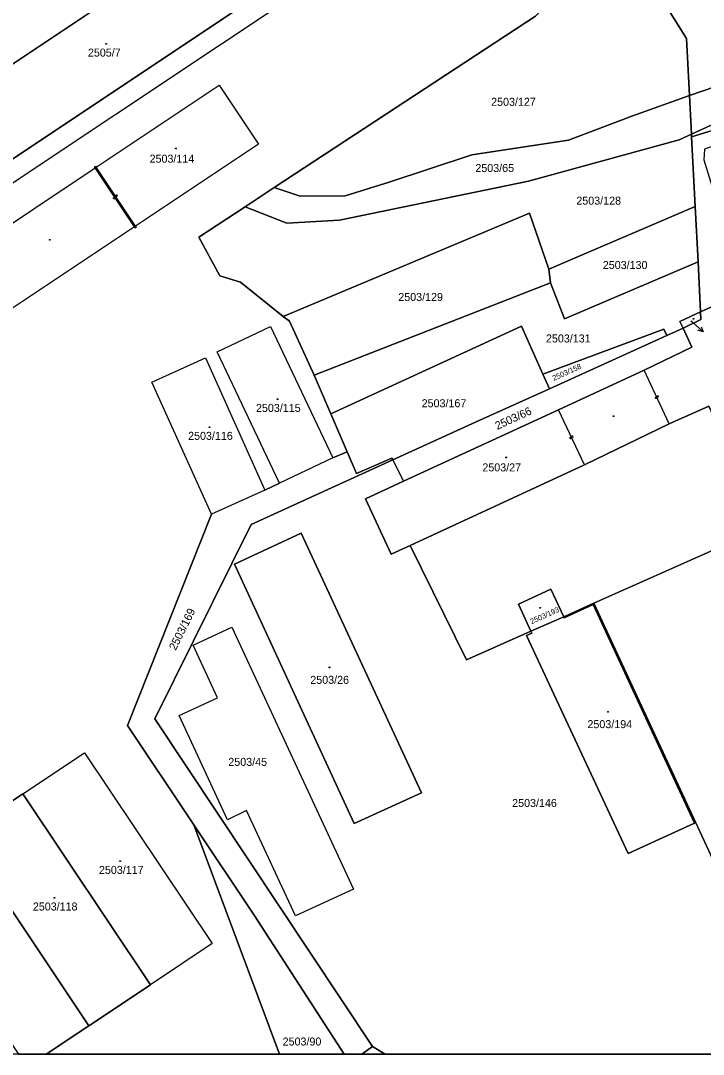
# Model space of a CAD drawing. Extents: x -596024 to -594475, y -1163820 to -1161957.
# Drawn here: x -595859.9 to -595715, y -1163820.2 to -1163600.7 of the extents above; entities that cross this region are included whole.
import ezdxf

# ---------------------------------------------------------------- set-up
doc = ezdxf.new("R2010")
doc.units = 0
for name, color, linetype in [('Level 1', 7, 'Continuous'), ('Level 13', 7, 'Continuous'), ('Level 3', 7, 'Continuous'), ('Level 4', 7, 'Continuous'), ('Level 5', 7, 'Continuous'), ('Level 57', 7, 'Continuous'), ('Level 60', 7, 'Continuous'), ('Vrstva 60', 7, 'Continuous'), ('Vrstva 63', 7, 'Continuous')]:
    doc.layers.add(name, color=color, linetype=linetype)

msp = doc.modelspace()

# ---------------------------------------------------------------- linework, layer by layer
at = {"layer": 'Level 1'}
for p, q in [((-595804.96, -1163820.23), (-595823.13, -1163771.52)), ((-595845.44, -1163814.2), (-595854.47, -1163820.23)), ((-595787.47, -1163820.23), (-595785.2, -1163818.59)), ((-595782.49, -1163820.23), (-595785.2, -1163818.59))]:
    msp.add_line(p, q, dxfattribs=at)
for points in [[(-595747.71, -1163559.45), (-595779.54, -1163580.65), (-595794.81, -1163590.75), (-595884.83, -1163650.71), (-595898.68, -1163630.68)], [(-595882.06, -1163623.58), (-595809.58, -1163575.23), (-595800.28, -1163589.15), (-595877.77, -1163640.84), (-595886.1, -1163628.4)], [(-595732.35, -1163582.47), (-595718.5, -1163604.56), (-595717.89, -1163616.66)], [(-595750.6, -1163599.77), (-595806.04, -1163636.18)], [(-595694.99, -1163605.67), (-595707.37, -1163613.03), (-595717.89, -1163616.66)], [(-595683.26, -1163606.91), (-595697.36, -1163615.67), (-595717.47, -1163624.86)], [(-595666.6, -1163609.76), (-595717.44, -1163625.43)], [(-595843.85, -1163631.82), (-595817.77, -1163614.42), (-595809.41, -1163626.95), (-595835.49, -1163644.35)], [(-595717.89, -1163616.66), (-595730.15, -1163621.02), (-595743.61, -1163626.13), (-595764.11, -1163629.2), (-595781.68, -1163635.06), (-595791.02, -1163637.97), (-595800.58, -1163638), (-595806.04, -1163636.18)], [(-595717.47, -1163624.86), (-595717.89, -1163616.66)], [(-595812.22, -1163640.24), (-595803.39, -1163643.76), (-595792.23, -1163643.09), (-595752.06, -1163634.84), (-595720.06, -1163626.04), (-595717.47, -1163624.86)], [(-595717.44, -1163625.43), (-595717.47, -1163624.86)], [(-595716.69, -1163640.21), (-595717.44, -1163625.43)], [(-595835.74, -1163644.51), (-595861.82, -1163661.91), (-595870.18, -1163649.38), (-595844.07, -1163631.97)], [(-595844.07, -1163631.97), (-595844.21, -1163631.76), (-595843.99, -1163631.61), (-595843.85, -1163631.82)], [(-595806.04, -1163636.18), (-595812.22, -1163640.24)], [(-595812.22, -1163640.24), (-595822.04, -1163646.69), (-595817.61, -1163654.91), (-595813.25, -1163656.26), (-595804.17, -1163663.57)], [(-595716.69, -1163640.21), (-595747.78, -1163653.48)], [(-595716.09, -1163651.96), (-595716.69, -1163640.21)], [(-595747.78, -1163653.48), (-595751.85, -1163641.63), (-595804.17, -1163663.57)], [(-595835.49, -1163644.35), (-595835.31, -1163644.61), (-595835.55, -1163644.81), (-595835.74, -1163644.51)], [(-595747.43, -1163656.44), (-595744.41, -1163664.02), (-595716.09, -1163651.96)], [(-595715.55, -1163662.6), (-595716.09, -1163651.96)], [(-595747.78, -1163653.48), (-595747.43, -1163656.44)], [(-595797.59, -1163676.03), (-595747.43, -1163656.44)], [(-595706.28, -1163658.38), (-595715.55, -1163662.6)], [(-595705.1, -1163660.92), (-595700.26, -1163671.29), (-595699.33, -1163673.05), (-595701.62, -1163674.12), (-595693.05, -1163691.78), (-595706.43, -1163698.34), (-595713.8, -1163682.6), (-595722.2, -1163686.36)], [(-595719.27, -1163666.01), (-595719.93, -1163664.6), (-595715.55, -1163662.6)], [(-595719.27, -1163666.01), (-595715.47, -1163664.21), (-595715.55, -1163662.6)], [(-595804.17, -1163663.57), (-595802.83, -1163664.52), (-595797.59, -1163676.03)], [(-595794.05, -1163684.25), (-595753.54, -1163665.59), (-595749.04, -1163675.79)], [(-595804.95, -1163698.95), (-595818.18, -1163671.07), (-595806.86, -1163665.7), (-595793.64, -1163693.58)], [(-595749.04, -1163675.79), (-595723.33, -1163666.22), (-595722.71, -1163667.58)], [(-595722.71, -1163667.58), (-595747.65, -1163678.92)], [(-595719.27, -1163666.01), (-595717.37, -1163670.08), (-595727.49, -1163674.98)], [(-595719.27, -1163666.01), (-595722.71, -1163667.58)], [(-595819.4, -1163705.53), (-595832.03, -1163677.52), (-595820.66, -1163672.3), (-595808.02, -1163700.4)], [(-595797.59, -1163676.03), (-595794.05, -1163684.25)], [(-595749.04, -1163675.79), (-595747.65, -1163678.92)], [(-595727.49, -1163674.98), (-595745.74, -1163683.39)], [(-595747.65, -1163678.92), (-595763.17, -1163685.94), (-595780.87, -1163694)], [(-595794.05, -1163684.25), (-595790.59, -1163692.26)], [(-595745.74, -1163683.39), (-595778.62, -1163698.55)], [(-595740.2, -1163695.04), (-595722.2, -1163686.36)], [(-595780.87, -1163694), (-595810.95, -1163707.71), (-595831.44, -1163748.97), (-595785.2, -1163818.59)], [(-595793.64, -1163693.58), (-595804.95, -1163698.95)], [(-595790.59, -1163692.26), (-595793.64, -1163693.58)], [(-595790.59, -1163692.26), (-595788.59, -1163696.9), (-595781.06, -1163693.62), (-595780.87, -1163694)], [(-595780.87, -1163694), (-595778.62, -1163698.55)], [(-595777.17, -1163712.16), (-595740.2, -1163695.04)], [(-595778.62, -1163698.55), (-595786.71, -1163702.28), (-595781.26, -1163714.03), (-595777.17, -1163712.16)], [(-595738.23, -1163724.46), (-595676.4, -1163696.94)], [(-595808.02, -1163700.4), (-595819.4, -1163705.53)], [(-595804.95, -1163698.95), (-595808.02, -1163700.4)], [(-595819.4, -1163705.53), (-595837.22, -1163750.4), (-595823.13, -1163771.52)], [(-595789.06, -1163771.21), (-595774.8, -1163764.71), (-595796.66, -1163717.51), (-595800.32, -1163709.6), (-595814.49, -1163716.16), (-595789.06, -1163771.21)], [(-595777.17, -1163712.16), (-595765.21, -1163736.47), (-595751.57, -1163730.4)], [(-595751.57, -1163730.4), (-595754.21, -1163724.63), (-595747.31, -1163721.44), (-595744.61, -1163727.3)], [(-595751.57, -1163730.4), (-595751.4, -1163730.77), (-595752.47, -1163731.28), (-595730.91, -1163777.57), (-595716.82, -1163771.11), (-595738.33, -1163724.73), (-595744.49, -1163727.57), (-595744.61, -1163727.3)], [(-595744.61, -1163727.3), (-595738.23, -1163724.46)], [(-595694.95, -1163817.56), (-595738.23, -1163724.46)], [(-595751.57, -1163730.4), (-595744.61, -1163727.3)], [(-595815.09, -1163729.53), (-595789.21, -1163785.13), (-595801.52, -1163790.81), (-595811.95, -1163768.45), (-595815.99, -1163770.42), (-595826.23, -1163748.29), (-595818.12, -1163744.5), (-595823.28, -1163733.34), (-595815.09, -1163729.53)], [(-595859.45, -1163764.93), (-595846.32, -1163756.18), (-595819.26, -1163796.72), (-595832.34, -1163805.45)], [(-595859.45, -1163764.93), (-595872.49, -1163773.65)], [(-595832.34, -1163805.45), (-595859.45, -1163764.93)], [(-595791.24, -1163820.23), (-595810.34, -1163790.71), (-595823.13, -1163771.52)], [(-595872.49, -1163773.65), (-595845.44, -1163814.2)], [(-595845.44, -1163814.2), (-595832.34, -1163805.45)]]:
    msp.add_lwpolyline(points, dxfattribs=at)
at = {"layer": 'Level 13'}
for centre, start, end in [((-595840.05, -1163638.34), 160.9678, 33.0658), ((-595839.82, -1163638.18), 161.0839, 33.1819), ((-595839.75, -1163638.14), 340.7533, 213.3433), ((-595839.52, -1163637.98), 340.8694, 213.4594), ((-595725.01, -1163680.75), 152.3041, 24.4021), ((-595724.67, -1163680.59), 332.0897, 204.6797), ((-595743.14, -1163689.3), 152.8055, 24.9035), ((-595742.8, -1163689.14), 332.5911, 205.1811)]:
    msp.add_arc(centre, 0.184, start, end, dxfattribs=at)
at = {"layer": 'Level 3'}
for points in [[(-595835.74, -1163644.51), (-595844.07, -1163631.97)], [(-595835.49, -1163644.35), (-595843.85, -1163631.82)], [(-595722.2, -1163686.36), (-595727.49, -1163674.98)], [(-595740.2, -1163695.04), (-595745.74, -1163683.39)]]:
    msp.add_lwpolyline(points, dxfattribs=at)
at = {"layer": 'Level 5'}
for centre, radius in [((-595841.74, -1163605.67), 0.09), ((-595841.74, -1163605.67), 0.0521), ((-595826.92, -1163627.88), 0.09), ((-595826.92, -1163627.88), 0.0521), ((-595853.69, -1163647.27), 0.09), ((-595853.69, -1163647.27), 0.0521), ((-595717.06, -1163664.05), 0.09), ((-595717.06, -1163664.05), 0.0521), ((-595805.34, -1163681.12), 0.09), ((-595805.34, -1163681.12), 0.0521), ((-595734.01, -1163684.71), 0.09), ((-595734.01, -1163684.71), 0.0521), ((-595819.79, -1163687.05), 0.09), ((-595819.79, -1163687.05), 0.0521), ((-595756.82, -1163693.48), 0.09), ((-595756.82, -1163693.48), 0.0521), ((-595749.6, -1163725.42), 0.09), ((-595749.6, -1163725.42), 0.0521), ((-595794.35, -1163738.07), 0.09), ((-595794.35, -1163738.07), 0.0521), ((-595735.2, -1163747.52), 0.09), ((-595735.2, -1163747.52), 0.0521), ((-595838.76, -1163779.22), 0.09), ((-595838.76, -1163779.22), 0.0521), ((-595852.73, -1163786.99), 0.09), ((-595852.73, -1163786.99), 0.0521)]:
    msp.add_circle(centre, radius, dxfattribs=at)
at = {"layer": 'Level 57'}
for p, q in [((-595717.59, -1163664.47), (-595717.25, -1163664.78)), ((-595717.25, -1163664.78), (-595715.02, -1163666.79))]:
    msp.add_line(p, q, dxfattribs=at)
msp.add_lwpolyline([(-595715.43, -1163665.75), (-595715.02, -1163666.79), (-595716.1, -1163666.49)], dxfattribs=at)
at = {"layer": 'Level 60'}
for points in [[(-595800.28, -1163589.15), (-595809.58, -1163575.23), (-595882.06, -1163623.58), (-595864.36, -1163602.49), (-595877.42, -1163591.6), (-595898.68, -1163630.68), (-595941.75, -1163568.24), (-595936.35, -1163564.52), (-595917.02, -1163551.71), (-595882.58, -1163528.73), (-595847.14, -1163505.05), (-595844.73, -1163503.41), (-595820.11, -1163487.1), (-595803.59, -1163476.01), (-595782.54, -1163507.01), (-595751.09, -1163554.35), (-595747.71, -1163559.45), (-595779.54, -1163580.65), (-595794.81, -1163590.75), (-595884.83, -1163650.71), (-595898.68, -1163630.68), (-595893.42, -1163637.11), (-595886.1, -1163628.4), (-595877.77, -1163640.84)], [(-595714.43, -1163592.23), (-595706.37, -1163597.35), (-595699.5, -1163596.77), (-595698.78, -1163598.28), (-595698.6, -1163598.19), (-595697.67, -1163600.15), (-595694.99, -1163605.67), (-595707.37, -1163613.03), (-595717.89, -1163616.66), (-595718.5, -1163604.56), (-595732.35, -1163582.47), (-595731.93, -1163581.71), (-595734.61, -1163575.4), (-595741.07, -1163559.59), (-595714.2, -1163540.24), (-595713.26, -1163541.29), (-595696.08, -1163567.12), (-595701.16, -1163571.13), (-595697.69, -1163575.73), (-595712.53, -1163582.6)], [(-595809.58, -1163575.23), (-595800.28, -1163589.15), (-595877.77, -1163640.84), (-595886.1, -1163628.4), (-595887.08, -1163626.93), (-595882.06, -1163623.58)], [(-595730.15, -1163621.02), (-595743.61, -1163626.13), (-595764.11, -1163629.2), (-595781.68, -1163635.06), (-595791.02, -1163637.97), (-595800.58, -1163638), (-595806.04, -1163636.18), (-595750.6, -1163599.77), (-595742.27, -1163590.91), (-595738.79, -1163596.27), (-595732.59, -1163592.25), (-595736.18, -1163586.19), (-595733.27, -1163584.1), (-595732.35, -1163582.47), (-595718.5, -1163604.56), (-595717.89, -1163616.66)], [(-595676.33, -1163602.6), (-595680.47, -1163596.27), (-595679.94, -1163595.12), (-595676.63, -1163587.9), (-595666.6, -1163609.76), (-595717.44, -1163625.43), (-595717.47, -1163624.86), (-595697.36, -1163615.67), (-595683.26, -1163606.91), (-595680.89, -1163611.42), (-595676.19, -1163608.96), (-595678.73, -1163604.09)], [(-595683.26, -1163606.91), (-595697.36, -1163615.67), (-595717.47, -1163624.86), (-595717.89, -1163616.66), (-595707.37, -1163613.03), (-595694.99, -1163605.67), (-595692.62, -1163610.53), (-595683.59, -1163606.28)], [(-595666.18, -1163610.67), (-595714.69, -1163628.02), (-595714.85, -1163630.3), (-595709.8, -1163646.67), (-595706.69, -1163656.78), (-595706.28, -1163658.38), (-595715.55, -1163662.6), (-595716.09, -1163651.96), (-595716.69, -1163640.21), (-595717.44, -1163625.43), (-595666.6, -1163609.76)], [(-595861.82, -1163661.91), (-595870.18, -1163649.38), (-595844.07, -1163631.97), (-595844.21, -1163631.76), (-595843.99, -1163631.61), (-595843.85, -1163631.82), (-595817.77, -1163614.42), (-595809.41, -1163626.95), (-595835.49, -1163644.35), (-595835.31, -1163644.61), (-595835.55, -1163644.81), (-595835.74, -1163644.51)], [(-595792.23, -1163643.09), (-595803.39, -1163643.76), (-595812.22, -1163640.24), (-595806.04, -1163636.18), (-595800.58, -1163638), (-595791.02, -1163637.97), (-595781.68, -1163635.06), (-595764.11, -1163629.2), (-595743.61, -1163626.13), (-595730.15, -1163621.02), (-595717.89, -1163616.66), (-595717.47, -1163624.86), (-595720.06, -1163626.04), (-595752.06, -1163634.84)], [(-595803.39, -1163643.76), (-595792.23, -1163643.09), (-595752.06, -1163634.84), (-595720.06, -1163626.04), (-595717.47, -1163624.86), (-595717.44, -1163625.43), (-595716.69, -1163640.21), (-595747.78, -1163653.48), (-595751.85, -1163641.63), (-595804.17, -1163663.57), (-595813.25, -1163656.26), (-595817.61, -1163654.91), (-595822.04, -1163646.69), (-595812.22, -1163640.24)], [(-595747.43, -1163656.44), (-595747.78, -1163653.48), (-595716.69, -1163640.21), (-595716.09, -1163651.96), (-595744.41, -1163664.02)], [(-595747.78, -1163653.48), (-595747.43, -1163656.44), (-595797.59, -1163676.03), (-595802.83, -1163664.52), (-595804.17, -1163663.57), (-595751.85, -1163641.63)], [(-595676.4, -1163696.94), (-595738.23, -1163724.46), (-595744.61, -1163727.3), (-595747.31, -1163721.44), (-595754.21, -1163724.63), (-595751.57, -1163730.4), (-595765.21, -1163736.47), (-595777.17, -1163712.16), (-595740.2, -1163695.04), (-595722.2, -1163686.36), (-595713.8, -1163682.6), (-595706.43, -1163698.34), (-595693.05, -1163691.78), (-595701.62, -1163674.12), (-595699.33, -1163673.05), (-595700.26, -1163671.29), (-595705.1, -1163660.92), (-595685.88, -1163657.72), (-595678.65, -1163655.24), (-595653.75, -1163647.05), (-595642.76, -1163682.1), (-595648.66, -1163684.69), (-595663.05, -1163691)], [(-595747.43, -1163656.44), (-595744.41, -1163664.02), (-595716.09, -1163651.96), (-595715.55, -1163662.6), (-595719.93, -1163664.6), (-595719.27, -1163666.01), (-595722.71, -1163667.58), (-595723.33, -1163666.22), (-595749.04, -1163675.79), (-595753.54, -1163665.59), (-595794.05, -1163684.25), (-595797.59, -1163676.03)], [(-595719.27, -1163666.01), (-595715.47, -1163664.21), (-595715.55, -1163662.6), (-595706.28, -1163658.38), (-595705.1, -1163660.92), (-595700.26, -1163671.29), (-595699.33, -1163673.05), (-595701.62, -1163674.12), (-595693.05, -1163691.78), (-595706.43, -1163698.34), (-595713.8, -1163682.6), (-595722.2, -1163686.36), (-595740.2, -1163695.04), (-595777.17, -1163712.16), (-595781.26, -1163714.03), (-595786.71, -1163702.28), (-595778.62, -1163698.55), (-595745.74, -1163683.39), (-595727.49, -1163674.98), (-595717.37, -1163670.08)], [(-595715.47, -1163664.21), (-595719.27, -1163666.01), (-595719.93, -1163664.6), (-595715.55, -1163662.6)], [(-595781.06, -1163693.62), (-595788.59, -1163696.9), (-595790.59, -1163692.26), (-595794.05, -1163684.25), (-595753.54, -1163665.59), (-595749.04, -1163675.79), (-595747.65, -1163678.92), (-595763.17, -1163685.94), (-595780.87, -1163694)], [(-595804.95, -1163698.95), (-595818.18, -1163671.07), (-595806.86, -1163665.7), (-595793.64, -1163693.58)], [(-595763.17, -1163685.94), (-595747.65, -1163678.92), (-595722.71, -1163667.58), (-595719.27, -1163666.01), (-595717.37, -1163670.08), (-595727.49, -1163674.98), (-595745.74, -1163683.39), (-595778.62, -1163698.55), (-595780.87, -1163694)], [(-595747.65, -1163678.92), (-595749.04, -1163675.79), (-595723.33, -1163666.22), (-595722.71, -1163667.58)], [(-595819.4, -1163705.53), (-595832.03, -1163677.52), (-595820.66, -1163672.3), (-595808.02, -1163700.4)], [(-595774.8, -1163764.71), (-595789.06, -1163771.21), (-595814.49, -1163716.16), (-595800.32, -1163709.6), (-595796.66, -1163717.51)], [(-595744.61, -1163727.3), (-595751.57, -1163730.4), (-595754.21, -1163724.63), (-595747.31, -1163721.44)], [(-595738.33, -1163724.73), (-595716.82, -1163771.11), (-595730.91, -1163777.57), (-595752.47, -1163731.28), (-595751.4, -1163730.77), (-595751.57, -1163730.4), (-595744.61, -1163727.3), (-595744.49, -1163727.57)], [(-595815.09, -1163729.53), (-595789.21, -1163785.13), (-595801.52, -1163790.81), (-595811.95, -1163768.45), (-595815.99, -1163770.42), (-595826.23, -1163748.29), (-595818.12, -1163744.5), (-595823.28, -1163733.34)], [(-595832.34, -1163805.45), (-595859.45, -1163764.93), (-595846.32, -1163756.18), (-595819.26, -1163796.72)], [(-595845.44, -1163814.2), (-595872.49, -1163773.65), (-595859.45, -1163764.93), (-595832.34, -1163805.45)]]:
    msp.add_lwpolyline(points, close=True, dxfattribs=at)
at = {"layer": 'Vrstva 60'}
for points in [[(-595794.81, -1163590.75), (-595884.83, -1163650.71), (-595898.68, -1163630.68), (-595941.75, -1163568.24)], [(-595872.49, -1163773.65), (-595859.45, -1163764.93), (-595846.32, -1163756.18), (-595819.26, -1163796.72), (-595832.34, -1163805.45), (-595845.44, -1163814.2), (-595854.47, -1163820.23), (-595804.96, -1163820.23), (-595823.13, -1163771.52), (-595837.22, -1163750.4), (-595819.4, -1163705.53), (-595832.03, -1163677.52), (-595820.66, -1163672.3), (-595808.02, -1163700.4), (-595804.95, -1163698.95), (-595818.18, -1163671.07), (-595806.86, -1163665.7), (-595793.64, -1163693.58), (-595790.59, -1163692.26), (-595794.05, -1163684.25), (-595797.59, -1163676.03), (-595802.83, -1163664.52), (-595804.17, -1163663.57), (-595813.25, -1163656.26), (-595817.61, -1163654.91), (-595822.04, -1163646.69), (-595812.22, -1163640.24), (-595806.04, -1163636.18), (-595750.6, -1163599.77)]]:
    msp.add_lwpolyline(points, dxfattribs=at)
for points in [[(-595844.07, -1163631.97), (-595844.21, -1163631.76), (-595843.99, -1163631.61), (-595843.85, -1163631.82), (-595817.77, -1163614.42), (-595809.41, -1163626.95), (-595835.49, -1163644.35), (-595835.31, -1163644.61), (-595835.55, -1163644.81), (-595835.74, -1163644.51), (-595861.82, -1163661.91), (-595870.18, -1163649.38)], [(-595791.24, -1163820.23), (-595787.47, -1163820.23), (-595785.2, -1163818.59), (-595831.44, -1163748.97), (-595810.95, -1163707.71), (-595780.87, -1163694), (-595781.06, -1163693.62), (-595788.59, -1163696.9), (-595790.59, -1163692.26), (-595793.64, -1163693.58), (-595804.95, -1163698.95), (-595808.02, -1163700.4), (-595819.4, -1163705.53), (-595837.22, -1163750.4), (-595823.13, -1163771.52), (-595810.34, -1163790.71)], [(-595782.49, -1163820.23), (-595700.6, -1163820.23), (-595694.95, -1163817.56), (-595738.23, -1163724.46), (-595744.61, -1163727.3), (-595744.49, -1163727.57), (-595738.33, -1163724.73), (-595716.82, -1163771.11), (-595730.91, -1163777.57), (-595752.47, -1163731.28), (-595751.4, -1163730.77), (-595751.57, -1163730.4), (-595765.21, -1163736.47), (-595777.17, -1163712.16), (-595781.26, -1163714.03), (-595786.71, -1163702.28), (-595778.62, -1163698.55), (-595780.87, -1163694), (-595810.95, -1163707.71), (-595831.44, -1163748.97), (-595785.2, -1163818.59)], [(-595675.88, -1163820.23), (-595583.01, -1163820.23), (-595582.45, -1163819.85), (-595579.98, -1163817.67), (-595577.78, -1163814.72), (-595575.54, -1163811.07), (-595575.2, -1163808.16), (-595577.61, -1163802.27), (-595576.91, -1163801.81), (-595616.59, -1163742.63), (-595620.13, -1163734.38), (-595621.54, -1163730.49), (-595625.28, -1163731.71), (-595639.56, -1163736.46), (-595656.2, -1163741.96), (-595658.09, -1163742.59), (-595675.81, -1163698.41), (-595676.4, -1163696.94), (-595738.23, -1163724.46), (-595694.95, -1163817.56), (-595680.39, -1163810.69)], [(-595814.49, -1163716.16), (-595800.32, -1163709.6), (-595796.66, -1163717.51), (-595774.8, -1163764.71), (-595789.06, -1163771.21)], [(-595801.52, -1163790.81), (-595811.95, -1163768.45), (-595815.99, -1163770.42), (-595826.23, -1163748.29), (-595818.12, -1163744.5), (-595823.28, -1163733.34), (-595815.09, -1163729.53), (-595789.21, -1163785.13)], [(-595804.96, -1163820.23), (-595791.24, -1163820.23), (-595810.34, -1163790.71), (-595823.13, -1163771.52)], [(-595860.32, -1163820.23), (-595854.47, -1163820.23), (-595845.44, -1163814.2), (-595872.49, -1163773.65), (-595885.57, -1163782.39)], [(-595787.47, -1163820.23), (-595782.49, -1163820.23), (-595785.2, -1163818.59)]]:
    msp.add_lwpolyline(points, close=True, dxfattribs=at)
at = {"layer": 'Vrstva 63'}
msp.add_lwpolyline([(-594475.47, -1163820.23), (-596024.42, -1163820.23), (-596024.42, -1161956.88), (-594475.47, -1161956.88)], close=True, dxfattribs=at)

# ---------------------------------------------------------------- texts
at = {"layer": 'Level 4'}
for s, height, p in [('2505/7', 1.7, (-595845.61, -1163608.37)), ('2503/127', 1.7, (-595760.01, -1163618.82)), ('2503/114', 1.7, (-595832.52, -1163630.9)), ('2503/65', 1.7, (-595763.36, -1163632.87)), ('2503/128', 1.7, (-595741.92, -1163639.81)), ('2503/130', 1.7, (-595736.3, -1163653.47)), ('2503/129', 1.7, (-595779.72, -1163660.27)), ('2503/57', 0.1, (-595717.59, -1163664.47)), ('2503/131', 1.7, (-595748.37, -1163669.07)), ('2503/167', 1.7, (-595774.76, -1163682.83)), ('2503/115', 1.7, (-595809.93, -1163683.82)), ('2503/116', 1.7, (-595824.34, -1163689.75)), ('2503/27', 1.7, (-595761.87, -1163696.45)), ('2503/26', 1.7, (-595798.4, -1163741.56)), ('2503/194', 1.7, (-595739.56, -1163750.97)), ('2503/45', 1.7, (-595815.8, -1163758.98)), ('2503/146', 1.7, (-595755.54, -1163767.71)), ('2503/117', 1.7, (-595843.27, -1163781.92)), ('2503/118', 1.7, (-595857.3, -1163789.69)), ('2503/90', 1.7, (-595804.27, -1163818.36))]:
    msp.add_text(s, height=height, dxfattribs=at).set_placement(p)
for s, height, rotation, p in [('2503/158', 1.14, 24.4919, (-595746.69, -1163677.26)), ('2503/66', 1.7, 24.7494, (-595758.7, -1163687.66)), ('2503/169', 1.7, 63.5907, (-595826.97, -1163734.57)), ('2503/193', 1.14, 24.4188, (-595751.41, -1163728.91))]:
    msp.add_text(s, height=height, rotation=rotation, dxfattribs=at).set_placement(p)

doc.saveas('drawing.dxf')
